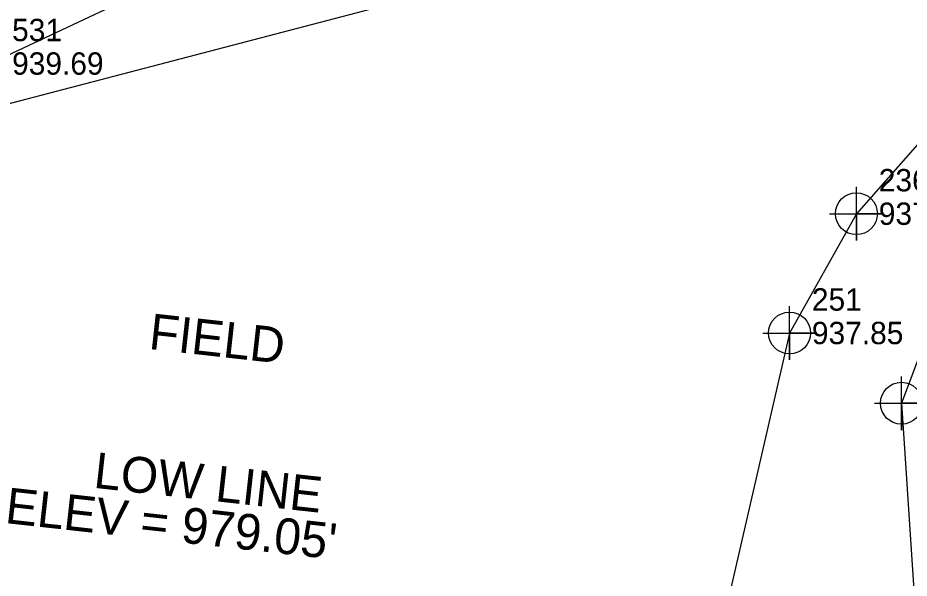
# Model space of a CAD drawing. Extents: x 1150279 to 1151282, y 654632 to 657999.
# Drawn here: x 1150667.5 to 1150767.1, y 657156.5 to 657219.1 of the extents above; entities that cross this region are included whole.
import ezdxf

# ---------------------------------------------------------------- set-up
doc = ezdxf.new("R2010")
doc.units = 0
for name, color, linetype in [('Exist Hydro Jurisdictional Stream or Body of Water', 7, 'Continuous'), ('Exist Hydro Stream or Body of Water', 7, 'Continuous'), ('Exist Hydro Stream or Body of Water Cogo Elevation', 7, 'Continuous'), ('Exist Hydro Stream or Body of Water Cogo Number', 7, 'Continuous'), ('Exist Hydro Stream or Body of Water Cogo Point CELL', 7, 'Continuous'), ('Exist Property Line', 7, 'Continuous'), ('Exist Utilities Other Located Object Text', 7, 'Continuous'), ('Exist Vegetation Woods Line Text', 7, 'Continuous')]:
    doc.layers.add(name, color=color, linetype=linetype)

msp = doc.modelspace()

# ---------------------------------------------------------------- linework, layer by layer
at = {"layer": 'Exist Hydro Jurisdictional Stream or Body of Water'}
for points in [[(1150876.787, 657253.089), (1150843.421, 657236.681), (1150801.483, 657213.293), (1150770.944, 657188.613), (1150766.225, 657176.03), (1150768.218, 657146.086), (1150768.306, 657144.46)], [(1150782.541, 657221.519), (1150761.192, 657197.223), (1150753.715, 657183.881), (1150744.98, 657145.957), (1150745.062, 657143.83)]]:
    msp.add_lwpolyline(points, dxfattribs=at)
at = {"layer": 'Exist Hydro Stream or Body of Water'}
msp.add_lwpolyline([(1150590.778, 657202.886), (1150604.11, 657206.022), (1150664.313, 657214.018), (1150690.761, 657226.457), (1150708.049, 657225.678), (1150725.138, 657224.28), (1150732.802, 657228.826), (1150747.961, 657235.28), (1150766.113, 657239.259), (1150781.02, 657229.668)], dxfattribs=at)
at = {"layer": 'Exist Hydro Stream or Body of Water Cogo Point CELL'}
for points in [[(1150758.192, 657197.223), (1150764.192, 657197.223), (1150761.192, 657197.223), (1150761.192, 657194.223), (1150761.192, 657200.223)], [(1150750.715, 657183.881), (1150756.715, 657183.881), (1150753.715, 657183.881), (1150753.715, 657180.881), (1150753.715, 657186.881)], [(1150763.225, 657176.03), (1150769.225, 657176.03), (1150766.225, 657176.03), (1150766.225, 657173.03), (1150766.225, 657179.03)]]:
    msp.add_lwpolyline(points, dxfattribs=at)
for centre in [(1150761.192, 657197.223), (1150753.715, 657183.881), (1150766.225, 657176.03)]:
    msp.add_circle(centre, 2.344, dxfattribs=at)
at = {"layer": 'Exist Property Line'}
msp.add_line((1150590.985, 657189.855), (1150860.406, 657260.228), dxfattribs=at)

# ---------------------------------------------------------------- texts
at = {"layer": 'Exist Hydro Stream or Body of Water Cogo Elevation'}
for s, p in [('939.69', (1150666.813, 657212.768)), ('937.93', (1150763.692, 657195.973)), ('937.85', (1150756.215, 657182.631))]:
    msp.add_text(s, height=2.5, dxfattribs=at).set_placement(p)
at = {"layer": 'Exist Hydro Stream or Body of Water Cogo Number'}
for s, p in [('531', (1150666.813, 657216.518)), ('236', (1150763.692, 657199.723)), ('251', (1150756.215, 657186.381))]:
    msp.add_text(s, height=2.5, dxfattribs=at).set_placement(p)
at = {"layer": 'Exist Utilities Other Located Object Text'}
for s, p in [('LOW LINE', (1150675.828, 657166.584)), ("ELEV = 979.05'", (1150665.933, 657162.641))]:
    msp.add_text(s, height=4, rotation=353.6867, dxfattribs=at).set_placement(p)
at = {"layer": 'Exist Vegetation Woods Line Text'}
msp.add_text('FIELD', height=4, rotation=353.6867, dxfattribs=at).set_placement((1150681.999, 657182.102))

doc.saveas('drawing.dxf')
